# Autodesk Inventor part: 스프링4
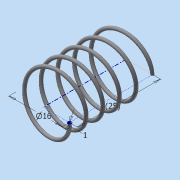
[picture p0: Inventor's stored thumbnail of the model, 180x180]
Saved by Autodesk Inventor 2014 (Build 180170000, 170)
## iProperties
Created: 2015-06
Part Number: 스프링4
Material: 강철, 연강
Document SubType Name: Modeling
Designer: Administrator
Density: 7.86 g/cm^3
Appearance: 강철
Mass: 1.53479 g
Surface Area: 7.89194 cm^2
Volume: 0.195266 cm^3
Author: Administrator
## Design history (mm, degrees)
sketch "스케치1"
  geometry: L1 (0, 0)-(8, 0); L2 (8, 0)-(8, 21.5); L3 (8, 21.5)-(0, 21.5); L4 (0, 21.5)-(0, 0); C1 r 0.5 at (8, 0)
  constraints: 8 end point, 2 parallel, 1 centre point, 1 coincident, 1 horizontal, 1 perpendicular
  dimensions: "d0" = 1 diameter of C1; "d1" = 16 diameter of L2 L4; "d2" = 21.5 distance of L1.end L2.end (derived)
feature "코일1" sketch "스케치1" pitch "d3" = 10; turns "d5" = 5; dims "d4" = 21.5 (= d2), "d6" = 0, angle "d7" = 90 deg, angle "d8" = 90 deg, "d9" = 0, "d10" = 0
sketch "스케치2"
  geometry: L1 (-8.5, 0)-(-7.5, 0) reference; 1 further point
  constraints: 1 horizontal alignment
extrude "돌출1" cut sketch "스케치2" distance "d11" = 10; taper "d12" = 0 deg
node "작업 평면1"
sketch "스케치3"
  geometry: L1 (-7.5, 0)-(-8.5, 0) reference; 1 further point
  constraints: 1 horizontal alignment
extrude "돌출2" cut sketch "스케치3" distance "d14" = 10; taper "d15" = 0 deg
node "솔리드1"
node "절단 모서리 투영1"
node "절단 모서리 투영2"
other parameters: "d13" = 21.5 (= d2)
